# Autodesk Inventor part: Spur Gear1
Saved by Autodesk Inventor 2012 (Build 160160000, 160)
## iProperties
Created: 2011-12
Part Number: Spur Gear1
Material: Steel
Document SubType Name: Modeling
Designer: Admin
Categories: <?xml version="1.0" encoding="UTF-16"?> <MemberInstance><Categories><FamilyTemplate><FamilyTemplateParameter ValueType="xs:double" Id="1" ObjectReferenceKey="da
Density: 1 g/cm^3
CustomPartVersion: 1
Author: Admin
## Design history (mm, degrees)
sketch "Sketch1"
  geometry: C1 r 42 at (0, 0)
  constraints: 1 centre point
  dimensions: "d0" = 84 diameter of C1 (= da_da)
extrude "Extrusion1" new body sketch "Sketch1" distance "d1" = 25 (= da_b); taper "d2" = 0 deg
workplane "Work Plane2"
sketch "Sketch2"
  geometry: C1 r 42 at (0, 0) reference; C2 r 40 at (0, 0)
  constraints: 1 centre point, 1 coincident
  dimensions: "d3" = 80 diameter of C2 (= da_dw)
feature "Pitch Diameter" sketch "Sketch2" dims "d4" = 10, "d5" = 0
workplane "Work Plane8"
workplane "Work Plane9"
feature "Spur Gear" dims "da_b" = 25, "da_d" = 80, "da_aw" = 80, "da_da" = 84, "da_df" = 75, "da_dw" = 80, angle "da_beta" = 0 deg, "da_lefttooth" = 0, "da_righttooth" = 0
body "Solid1"
body "Srf1"
other parameters: "d17" = 0, "d34" = 4.5 deg (computed from da_z), "d39" = 0, "d41" = 0, "d47" = 0, "d48" = 0
